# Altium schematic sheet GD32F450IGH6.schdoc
size 127 x 101 mm
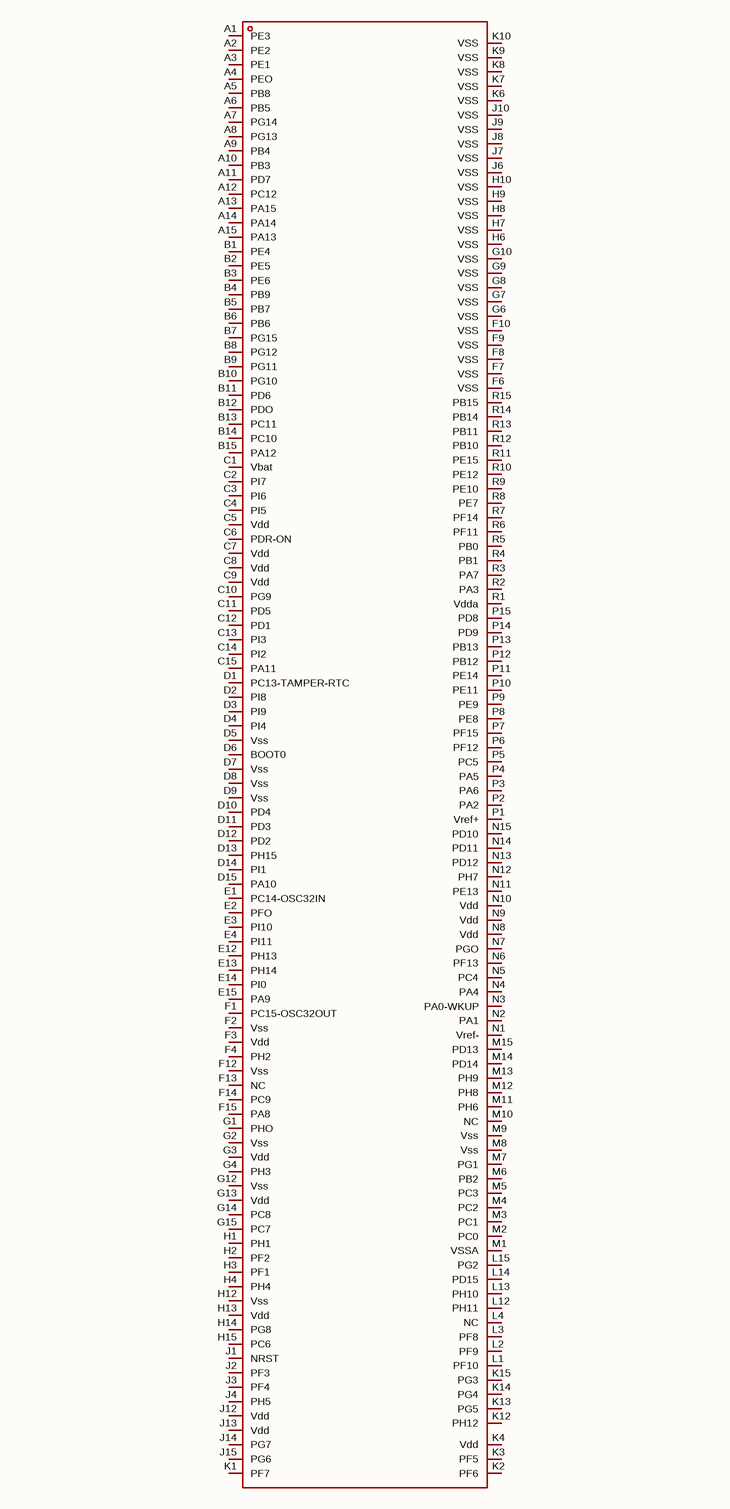
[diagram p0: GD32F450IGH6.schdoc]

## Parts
U?  gd32f450igh6  [BGA-201_L10.0-W10.0-P0.65-TL_GD32F450IGH6]  (value not drawn)

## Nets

Not connected (* = marked no-connect by the designer): U? A1(PE3) A2(PE2) A3(PE1) A4(PEO) A5(PB8) A6(PB5) A7(PG14) A8(PG13) A9(PB4) A10(PB3) A11(PD7) A12(PC12) A13(PA15) A14(PA14) A15(PA13) B1(PE4) B2(PE5) B3(PE6) B4(PB9) B5(PB7) B6(PB6) B7(PG15) B8(PG12) B9(PG11) B10(PG10) B11(PD6) B12(PDO) B13(PC11) B14(PC10) B15(PA12) C1(Vbat) C2(PI7) C3(PI6) C4(PI5) C5(Vdd) C6(PDR-ON) C7(Vdd) C8(Vdd) C9(Vdd) C10(PG9) C11(PD5) C12(PD1) C13(PI3) C14(PI2) C15(PA11) D1(PC13-TAMPER-RTC) D2(PI8) D3(PI9) D4(PI4) D5(Vss) D6(BOOT0) D7(Vss) D8(Vss) D9(Vss) D10(PD4) D11(PD3) D12(PD2) D13(PH15) D14(PI1) D15(PA10) E1(PC14-OSC32IN) E2(PFO) E3(PI10) E4(PI11) E12(PH13) E13(PH14) E14(PI0) E15(PA9) F1(PC15-OSC32OUT) F2(Vss) F3(Vdd) F4(PH2) F6(VSS) F7(VSS) F8(VSS) F9(VSS) F10(VSS) F12(Vss) F13(NC) F14(PC9) F15(PA8) G1(PHO) G2(Vss) G3(Vdd) G4(PH3) G6(VSS) G7(VSS) G8(VSS) G9(VSS) G10(VSS) G12(Vss) G13(Vdd) G14(PC8) G15(PC7) H1(PH1) H2(PF2) H3(PF1) H4(PH4) H6(VSS) H7(VSS) H8(VSS) H9(VSS) H10(VSS) H12(Vss) H13(Vdd) H14(PG8) H15(PC6) J1(NRST) J2(PF3) J3(PF4) J4(PH5) J6(VSS) J7(VSS) J8(VSS) J9(VSS) J10(VSS) J12(Vdd) J13(Vdd) J14(PG7) J15(PG6) K1(PF7) K2(PF6) K3(PF5) K4(Vdd) K6(VSS) K7(VSS) K8(VSS) K9(VSS) K10(VSS) K12(PH12) K13(PG5) K14(PG4) K15(PG3) L1(PF10) L2(PF9) L3(PF8) L4(NC) L12(PH11) L13(PH10) L14(PD15) L15(PG2) M1(VSSA) M2(PC0) M3(PC1) M4(PC2) M5(PC3) M6(PB2) M7(PG1) M8(Vss) M9(Vss) M10(NC) M11(PH6) M12(PH8) M13(PH9) M14(PD14) M15(PD13) N1(Vref-) N2(PA1) N3(PA0-WKUP) N4(PA4) N5(PC4) N6(PF13) N7(PGO) N8(Vdd) N9(Vdd) N10(Vdd) N11(PE13) N12(PH7) N13(PD12) N14(PD11) N15(PD10) P1(Vref+) P2(PA2) P3(PA6) P4(PA5) P5(PC5) P6(PF12) P7(PF15) P8(PE8) P9(PE9) P10(PE11) P11(PE14) P12(PB12) P13(PB13) P14(PD9) P15(PD8) R1(Vdda) R2(PA3) R3(PA7) R4(PB1) R5(PB0) R6(PF11) R7(PF14) R8(PE7) R9(PE10) R10(PE12) R11(PE15) R12(PB10) R13(PB11) R14(PB14) R15(PB15)

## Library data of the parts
U? = gd32f450igh6: CPU内核:ARM Cortex-M4;CPU最大主频:200MHz;; Manufacturer: GigaDevice(兆易创新); AddInBom: yes; ModelId: 88402b30fb10484d82a979771f4363d0; ModelName: UFBGA-201_L10.0-W10.0-H0.5-P0.65-TL_STM32H743IIK6; ModelTransform: 393.7,393.7,0,0,0,0,0,0,0; CPU Maximum Speed: 200MHz; Program Storage Size: 512KB; Program Memory Type: FLASH; Number of I/O: 140; ADC (Bit): 12bit; Voltage - Supply: 2.6V~3.6V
